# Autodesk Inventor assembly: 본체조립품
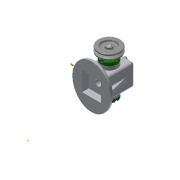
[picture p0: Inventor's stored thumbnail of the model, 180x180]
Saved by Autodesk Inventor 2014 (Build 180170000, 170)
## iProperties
Created: 2017-07
Part Number: 본체조립품
Document SubType Name: Assembly
Designer: user
Author: user
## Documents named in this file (16)
- C:\Users\user\Desktop\470707V1003\본체조립품.iam
- C:\Users\user\Desktop\470707V1003\V벨트풀리.ipt
- C:\Users\user\Desktop\470707V1003\고정핀 1.2 x  8.ipt
- C:\Users\user\Desktop\470707V1003\뒤커버.ipt
- C:\Users\user\Desktop\470707V1003\링크.ipt
- C:\Users\user\Desktop\470707V1003\멈춤나사 M3x8.ipt
- C:\Users\user\Desktop\470707V1003\베어링 12 x 32 x 10.ipt
- C:\Users\user\Desktop\470707V1003\본체.ipt
- C:\Users\user\Desktop\470707V1003\볼트 M4 x 12.ipt
- C:\Users\user\Desktop\470707V1003\부시.ipt
- C:\Users\user\Desktop\470707V1003\슬라이드.ipt
- C:\Users\user\Desktop\470707V1003\앞커버.ipt
- C:\Users\user\Desktop\470707V1003\오일실 12 25 7.ipt
- C:\Users\user\Desktop\470707V1003\키 4 x 4 x 10.ipt
- C:\Users\user\Desktop\470707V1003\편심축.ipt
- C:\Users\user\Desktop\470707V1003\핀 5 x 18.ipt
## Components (3 placed, 3 different names)
1. V벨트풀리:1 — Insert:8, Mate:2
2. 고정핀 1.2 x  8:1
3. 핀 5 x 18:1 — Insert:11
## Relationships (3: Insert 2, Mate 1)
- Insert:8: V벨트풀리:1
- Insert:11: 핀 5 x 18:1
- Mate:2: V벨트풀리:1
